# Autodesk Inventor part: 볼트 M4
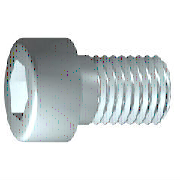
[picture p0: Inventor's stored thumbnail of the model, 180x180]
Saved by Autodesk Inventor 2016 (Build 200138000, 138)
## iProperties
IsCustomPart: 1
Created: 2012-02
Part Number: 볼트 M4
Material: 강철, 연강
Description: 6각머리 태핑 나사
Document SubType Name: Modeling
Standard: KS B 1003
Designer: mduedu
Standards Organization: KS
Language: ko-KR
Size Designation: M 4 x 10
Categories: <MemberInstance><Categories><Category DisplayName="조임쇠" InternalName="e4da775c-781d-43d5-af7c-5136215cf5a6" Mnemonic="FSTN"><Category DisplayName="볼트" InternalN
Density: 7.85 g/cm^3
Appearance: 강철
Mass: 2.03451 g
Surface Area: 3.0572 cm^2
Volume: 0.259174 cm^3
Author: mduedu
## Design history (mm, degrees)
sketch "스케치1"
  geometry: L1 (-1, 0)-(10, 0); L2 (10, 0)-(10, 2); L3 (10, 2)-(1.75, 2); L4 (1.75, 2)-(1.32, 2); L5 (1.32, 2)-(0, 2); L6 (0, 2)-(0, 3.5); L7 (0, 3.5)-(-4, 3.5); L8 (-4, 3.5)-(-4, 1.732); L9 (-4, 1.732)-(-2, 1.732); L10 (-2, 1.732)-(-1, 0); L11 (-6.8, 0)-(12.8, 0) reference; L12 (0, -0.7)-(0, 4.2) reference; L13 (1.75, 2)-(0, 2)
  constraints: 22 end point, 6 parallel, 2 collinear, 2 perpendicular, 1 horizontal, 1 point on line
  dimensions: "d1" = 8.25 distance from line of L3.end L2 (= GEL); "d2" = 0.42952 distance of L4.end L3.end (computed from GAL); "d3" = 4 distance between parallel lines of L8 L6 (= KOH); "d4" = 2 distance of L8.end L9.end (= INTI); "d5" = 60 deg angle of L10 L1; "d6" = 4 diameter of L3 L1 (= GD); "d7" = 4 diameter of L5 L1 (= BDM); "d8" = 3.4641 diameter of L9 L1 (= 1.1547 x SW); "d9" = 7 diameter of L7 L1 (= KOD); "d26" = 10 distance between parallel lines of L12 L2 (= NLG)
revolve "본체" sketch "스케치1" stored, may be unused: angle "d10" = 90 deg
sketch "스케치2"
  geometry: L1 (0, -4.9)-(0, 4.9) reference; L2 (-4.9, 0)-(4.9, 0) reference; L3 (1.732, 0)-(0.866, -1.5); L4 (0.866, -1.5)-(-0.866, -1.5); L5 (-0.866, -1.5)-(-1.732, 0); L6 (-1.732, 0)-(-0.866, 1.5); L7 (-0.866, 1.5)-(0.866, 1.5); L8 (0.866, 1.5)-(1.732, 0); 2 further points
  constraints: 12 end point, 1 coincident, 1 horizontal alignment, 1 point on line, 12 other
extrude "슬롯" join sketch "스케치2" stored distance "d11" = 10; taper "d12" = 0 deg
workplane "Work Plane1"
fillet "Fillet2" dims "d30" = 0.1 (= R)
body "Solid1"
fillet "모깎기1" dims "d17" = 0.4 (= RR)
feature "스레드" dims "d13" = 8.25 (= GEL), "d14" = 0
chamfer "모따기1" distance "d15" = 0.42941 (= -0.5 x SPD + 0.5 x GD); stored, may be unused: second distance "d16" = 0.42941 (= GUL), angle "d27" = 45 deg
other parameters: "GD" = 4 (= NND) [user parameter; used in 2 equation terms], "NLG" = 10 [user parameter; used in 1 equation term], "GEL" = 8.25 [user parameter; used in 2 equation terms], "KOD" = 7 [user parameter; used in 1 equation term], "KOH" = 4 [user parameter; used in 1 equation term], "INTI" = 2 [user parameter; used in 1 equation term], "GAL" = 0.42941 (= 0.61345 x PTC) [user parameter; used in 1 equation term], "GUL" = 0.42941 (= 0.61345 x PTC) [user parameter; used in 1 equation term], "BDM" = 4 (= NND) [user parameter; used in 1 equation term], "SW" = 3 [user parameter; used in 2 equation terms], "RR" = 0.4 [user parameter; used in 1 equation term], "SPD" = 3.14117 (= NND - 1.2269 x PTC) [user parameter; used in 1 equation term], "d19" = 0, "d28" = 0, "d29" = 0, "R" = 0.1 [user parameter; used in 1 equation term], "PHH" = 0.2 [user parameter], "GD1" = 3.14117 (= THREADDIA - 1.2269 x PTC) [user parameter], "THREADDIA" = 4 [user parameter; used in 1 equation term], "FAWI" = 45 deg [user parameter], "TPU" = 14.28571 (computed from PTC) [user parameter], "PTC" = 0.7 [user parameter; used in 5 equation terms], "NND" = 4 [user parameter; used in 3 equation terms], "TOA" = 30 deg [user parameter], "E0" = 3.465 (= 1.155 x SW) [user parameter]
